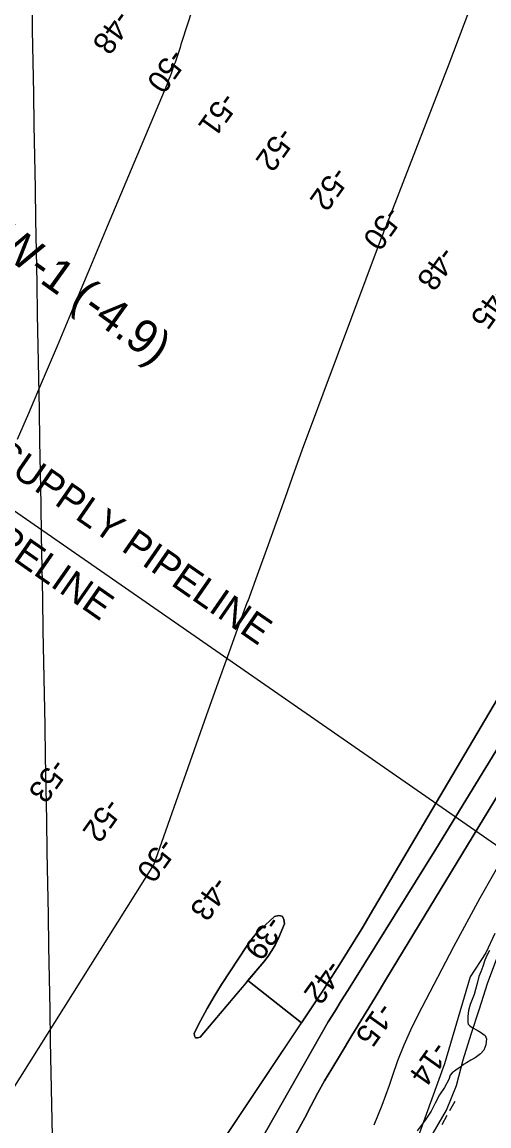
# Model space of a CAD drawing. Extents: x 3923531 to 3943530, y 207391 to 229799.
# Drawn here: x 3935604 to 3936304, y 218207 to 219861 of the extents above; entities that cross this region are included whole.
import ezdxf

# ---------------------------------------------------------------- set-up
doc = ezdxf.new("R2010")
doc.units = 0
for name, color, linetype in [('V-CHAN-NAID', 7, 'Continuous'), ('V-GRID-MAJR', 7, 'Continuous'), ('V-RIVR-EDGE', 7, 'Continuous'), ('V-RIVR-RANG', 7, 'Continuous'), ('V-RRAP-FSHR', 7, 'Continuous'), ('V-TOPO-DPTH', 7, 'Continuous'), ('V-TOPO-MAJR', 7, 'Continuous'), ('V-TOPO-MINR', 7, 'Continuous'), ('V-UTIL-IDEN', 7, 'Continuous'), ('V-UTIL-LINE', 7, 'Continuous'), ('V-WETL-SWMP', 7, 'Continuous')]:
    doc.layers.add(name, color=color, linetype=linetype)

msp = doc.modelspace()

# ---------------------------------------------------------------- linework, layer by layer
at = {"layer": 'V-GRID-MAJR'}
msp.add_spline([(3935779.9, 210874.8), (3935760.8, 211942.6), (3935652.4, 218002.6), (3935544, 224062.6), (3935501.8, 226418.9)], degree=3, dxfattribs=at)
at = {"layer": 'V-RIVR-EDGE'}
msp.add_lwpolyline([(3936312.5, 218495.6), (3936299, 218466.4), (3936275.4, 218430.4), (3936237.2, 218300.1), (3936199, 218195.6)], dxfattribs=at)
at = {"layer": 'V-RRAP-FSHR'}
msp.add_lwpolyline([(3935867.2, 217663.2), (3935890.1, 217695.9), (3935913.4, 217728.7), (3935936, 217761.5), (3935959.5, 217793.8), (3935982.9, 217826.2), (3936006.4, 217858.6), (3936029.9, 217891.3), (3936053.4, 217923.4), (3936076.8, 217955.8), (3936098.9, 217989.7), (3936119.2, 218023.5), (3936139.5, 218058.4), (3936159.8, 218092.5), (3936180.1, 218126.9), (3936200.3, 218161.5), (3936220.1, 218196.2), (3936240.2, 218230.9), (3936254.8, 218267.7), (3936265.2, 218306.4), (3936276.9, 218344.6), (3936289.3, 218382.6), (3936301.7, 218420.7), (3936315.4, 218458.1)], dxfattribs=at)
at = {"layer": 'V-TOPO-DPTH'}
for points in [[(3935703.2, 217883.8), (3936053.5, 218408.4), (3936055, 218410.6), (3936056.5, 218412.9), (3936058, 218415.2), (3936059.4, 218417.5), (3936080, 218449.7), (3936091.7, 218468.1), (3936103.2, 218486.7), (3936114.6, 218505.3), (3936125.7, 218524), (3936538.2, 219223)], [(3936538.2, 219223), (3936125.7, 218524), (3936114.6, 218505.3), (3936103.2, 218486.7), (3936091.7, 218468.1), (3936080, 218449.7), (3936059.4, 218417.5), (3936058, 218415.2), (3936056.5, 218412.9), (3936055, 218410.6), (3936053.5, 218408.4), (3936022.4, 218361.8)], [(3936579.3, 219134.3), (3936150.3, 218428.2), (3936133, 218399.7), (3936115.6, 218371.1), (3936098.2, 218342.6), (3936080.9, 218314.1), (3936068, 218293), (3936057.3, 218274.9), (3936047, 218256.6), (3936037.1, 218238), (3936027.6, 218219.2), (3935663.1, 217561.3)], [(3935659.1, 217653.3), (3936062.6, 218363.2), (3936072.5, 218378.9), (3936082.3, 218394.6), (3936092.2, 218410.4), (3936102, 218426.1), (3936223.8, 218621.9), (3936284, 218719.6), (3936343.8, 218817.6)], [(3936343.8, 218817.6), (3936284, 218719.6), (3936223.8, 218621.9), (3936102, 218426.1), (3936092.2, 218410.4), (3936082.3, 218394.6), (3936072.5, 218378.9), (3936062.6, 218363.2), (3935659.1, 217653.3)], [(3935978.3, 218470), (3935972.5, 218461.4), (3935966, 218453), (3935870.9, 218340.4), (3935866.8, 218339.1), (3935863.8, 218339.4), (3935862.4, 218342), (3935861.9, 218346.2), (3935871.3, 218364.9), (3935881.2, 218383.3), (3935891.8, 218401.4), (3935902.8, 218419.1), (3935940.9, 218477.7), (3935945.5, 218484.2), (3935950.4, 218490.5), (3935955.8, 218496.4), (3935961.5, 218502), (3935981.9, 218520.8), (3935988.7, 218522.4), (3935993.8, 218521.6), (3935996.3, 218517.1), (3935997, 218510.1), (3935988, 218488.7), (3935983.4, 218479.2), (3935978.3, 218470)], [(3935978.3, 218470), (3935983.4, 218479.2), (3935988, 218488.7), (3935997, 218510.1), (3935996.3, 218517.1), (3935993.8, 218521.6), (3935988.7, 218522.4), (3935981.9, 218520.8), (3935961.5, 218502), (3935955.8, 218496.4), (3935950.4, 218490.5), (3935945.5, 218484.2), (3935940.9, 218477.7), (3935902.8, 218419.1), (3935891.8, 218401.4), (3935881.2, 218383.3), (3935871.3, 218364.9), (3935861.9, 218346.2), (3935862.4, 218342), (3935863.8, 218339.4), (3935866.8, 218339.1), (3935870.9, 218340.4), (3935939.9, 218422.1), (3935942.3, 218425), (3936022.4, 218361.8), (3936019.8, 218357.9)], [(3936022.4, 218361.8), (3935942.3, 218425), (3935966, 218453), (3935972.5, 218461.4), (3935978.3, 218470)], [(3936019.8, 218357.9), (3935703.2, 217883.8)]]:
    msp.add_lwpolyline(points, dxfattribs=at)
at = {"layer": 'V-TOPO-MAJR'}
for points in [[(3935904.7, 220021.2), (3935843.4, 219832.3), (3935841.9, 219827.8), (3935840.5, 219823.3), (3935839, 219818.8), (3935837.6, 219814.3), (3935836.1, 219809.9), (3935834.6, 219805.4), (3935833, 219800.9), (3935831.4, 219796.5), (3935827, 219784.3), (3935825.5, 219780.1), (3935823.9, 219775.9), (3935822.2, 219771.7), (3935820.5, 219767.5), (3935731.4, 219554.9), (3935706.3, 219495.2), (3935681.2, 219435.5), (3935656, 219375.9), (3935630.7, 219316.2), (3935613.1, 219274.9), (3935596.4, 219236)], [(3935492.7, 218108.6), (3935801.4, 218598.6), (3935883.3, 218830.8), (3935897.6, 218871.1), (3935912, 218911.3), (3935926.6, 218951.4), (3935941.3, 218991.5), (3935942.4, 218994.3), (3935956.6, 219033), (3935970.7, 219071.7), (3935984.6, 219110.5), (3935998.5, 219149.3), (3936012.3, 219188), (3936026.3, 219226.8), (3936040.5, 219265.4), (3936054.9, 219304), (3936141.1, 219534), (3936142.8, 219538.4), (3936144.4, 219542.7), (3936146.1, 219547), (3936147.8, 219551.3), (3936148.4, 219552.8), (3936149.9, 219556.4), (3936151.3, 219559.9), (3936152.7, 219563.5), (3936154.1, 219567), (3936155.5, 219570.6), (3936156.9, 219574.1), (3936158.3, 219577.7), (3936159.7, 219581.2), (3936244, 219798.5), (3936266.7, 219858.3), (3936289, 219918.2)]]:
    msp.add_lwpolyline(points, dxfattribs=at)
at = {"layer": 'V-TOPO-MINR'}
for points in [[(3935703.2, 217883.8), (3936053.5, 218408.4), (3936055, 218410.6), (3936056.5, 218412.9), (3936058, 218415.2), (3936059.4, 218417.5), (3936080, 218449.7), (3936091.7, 218468.1), (3936103.2, 218486.7), (3936114.6, 218505.3), (3936125.7, 218524), (3936538.2, 219223)], [(3935663.1, 217561.3), (3936027.6, 218219.2), (3936037.1, 218238), (3936047, 218256.6), (3936057.3, 218274.9), (3936068, 218293), (3936080.9, 218314.1), (3936098.2, 218342.6), (3936115.6, 218371.1), (3936133, 218399.7), (3936150.3, 218428.2), (3936579.3, 219134.3)], [(3935659.1, 217653.3), (3936062.6, 218363.2), (3936072.5, 218378.9), (3936082.3, 218394.6), (3936092.2, 218410.4), (3936102, 218426.1), (3936223.8, 218621.9), (3936284, 218719.6), (3936343.8, 218817.6)], [(3936131.6, 218208.9), (3936143.8, 218238.4), (3936154.7, 218268.5), (3936159, 218281.9), (3936167.3, 218305.4), (3936176.4, 218328.7), (3936186.6, 218351.4), (3936197.6, 218373.9), (3936250.9, 218476.3), (3936290.4, 218549), (3936331.5, 218620.7)], [(3935978.3, 218470), (3935972.5, 218461.4), (3935966, 218453), (3935870.9, 218340.4), (3935866.8, 218339.1), (3935863.8, 218339.4), (3935862.4, 218342), (3935861.9, 218346.2), (3935871.3, 218364.9), (3935881.2, 218383.3), (3935891.8, 218401.4), (3935902.8, 218419.1), (3935940.9, 218477.7), (3935945.5, 218484.2), (3935950.4, 218490.5), (3935955.8, 218496.4), (3935961.5, 218502), (3935981.9, 218520.8), (3935988.7, 218522.4), (3935993.8, 218521.6), (3935996.3, 218517.1), (3935997, 218510.1), (3935988, 218488.7), (3935983.4, 218479.2), (3935978.3, 218470)]]:
    msp.add_lwpolyline(points, dxfattribs=at)
at = {"layer": 'V-UTIL-LINE'}
msp.add_lwpolyline([(3936739.3, 218357.7), (3936622.1, 218414.6), (3934986.4, 219548.1), (3933485.3, 218734.8), (3932852, 218820.9)], dxfattribs=at)
at = {"layer": 'V-WETL-SWMP'}
for p, q in [((3936297.7, 218455.4), (3936294.5, 218446)), ((3936300.6, 218462.7), (3936297.7, 218455.4)), ((3936304.7, 218470.2), (3936300.6, 218462.7)), ((3936291.4, 218438.3), (3936288.5, 218431.1)), ((3936294.5, 218446), (3936291.4, 218438.3)), ((3936288.5, 218431.1), (3936285.8, 218420.6)), ((3936283.7, 218411.7), (3936281.5, 218404.3)), ((3936285.8, 218420.6), (3936283.7, 218411.7)), ((3936275.5, 218389), (3936273.1, 218380.3)), ((3936279.4, 218399.1), (3936275.5, 218389)), ((3936281.5, 218404.3), (3936279.4, 218399.1)), ((3936273.1, 218380.3), (3936272, 218371.1)), ((3936272, 218371.1), (3936271.9, 218362.3)), ((3936271.9, 218362.3), (3936272.4, 218359.9)), ((3936272.4, 218359.9), (3936274.4, 218357.7)), ((3936274.4, 218357.7), (3936278.6, 218354.7)), ((3936278.6, 218354.7), (3936285.9, 218350.6)), ((3936285.9, 218350.6), (3936291.1, 218347.8)), ((3936291.1, 218347.8), (3936298, 218342.5)), ((3936298, 218342.5), (3936299.9, 218337.7)), ((3936299.2, 218328.8), (3936295.8, 218320.6)), ((3936299.9, 218337.7), (3936299.2, 218328.8)), ((3936276.3, 218305.7), (3936270.2, 218301.8)), ((3936282.9, 218309.4), (3936276.3, 218305.7)), ((3936291.1, 218315.5), (3936282.9, 218309.4)), ((3936295.8, 218320.6), (3936291.1, 218315.5)), ((3936253.8, 218291), (3936248.6, 218286.8)), ((3936261.8, 218296.3), (3936253.8, 218291)), ((3936265.6, 218299.2), (3936261.8, 218296.3)), ((3936270.2, 218301.8), (3936265.6, 218299.2)), ((3936243.3, 218276.7), (3936237, 218265)), ((3936245.7, 218283.3), (3936243.3, 218276.7)), ((3936248.6, 218286.8), (3936245.7, 218283.3)), ((3936237, 218265), (3936229.7, 218253.7)), ((3936223, 218241.2), (3936217.1, 218229.3)), ((3936229.7, 218253.7), (3936223, 218241.2)), ((3936252.4, 218243.9), (3936244.6, 218229.9)), ((3936217.1, 218229.3), (3936207.8, 218215.9)), ((3936240.7, 218222.9), (3936232.9, 218209)), ((3936207.8, 218215.9), (3936196, 218200.1))]:
    msp.add_line(p, q, dxfattribs=at)

# ---------------------------------------------------------------- texts
at = {"layer": 'V-CHAN-NAID'}
msp.add_text('POGO W-1 (-4.9)', height=50, rotation=324.301, dxfattribs=at).set_placement((3935381.1, 219649.8))
at = {"layer": 'V-RIVR-RANG'}
for s, rotation, p in [('-48', 234.3985, (3935745.2, 219881.7)), ('-50', 234.3985, (3935826.7, 219823.9)), ('-51', 234.3985, (3935903.8, 219758.7)), ('-52', 234.3985, (3935989.9, 219706.4)), ('-52', 234.3985, (3936071, 219647.4)), ('-50', 234.3985, (3936150.7, 219588.2)), ('-48', 234.3985, (3936231.8, 219527.7)), ('-45', 234.3985, (3936312, 219470)), ('-53', 234.3985, (3935649.4, 218760.3)), ('-52', 234.3985, (3935730.4, 218701.2)), ('-50', 234.3985, (3935811.5, 218641.3)), ('-43', 234.3985, (3935891.5, 218583.5)), ('-39', 234.3985, (3935972.8, 218524.7)), ('-42', 234.5983, (3936061.9, 218458.7)), ('-15', 234.5983, (3936139.3, 218395)), ('-14', 234.5983, (3936220.4, 218336.5))]:
    msp.add_text(s, height=33.5, rotation=rotation, dxfattribs=at).set_placement(p)
at = {"layer": 'V-UTIL-IDEN'}
for s, rotation, p in [('CHEVERON SUPPLY PIPELINE', 325.3283, (3935281, 219395)), ('1-8" OIL PIPELINE', 325.0908, (3935331.2, 219235.3))]:
    msp.add_text(s, height=42, rotation=rotation, dxfattribs=at).set_placement(p)

doc.saveas('drawing.dxf')
